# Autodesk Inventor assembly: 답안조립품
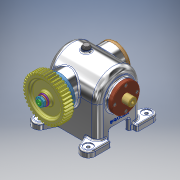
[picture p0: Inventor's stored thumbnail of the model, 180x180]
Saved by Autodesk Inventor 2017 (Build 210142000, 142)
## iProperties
Part Number: 답안조립품
Material: 일반
Document SubType Name: Assembly
Designer: MRC
Author: MRC
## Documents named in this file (17)
- C:\Users\MRC\Downloads\740904V1001\답안조립품.iam
- C:\Users\MRC\Downloads\740904V1001\본체.ipt
- C:\Users\MRC\Downloads\740904V1001\깊은 홈 볼베어링 6203.ipt
- C:\Users\MRC\Downloads\740904V1001\편심축.ipt
- C:\Users\MRC\Downloads\740904V1001\뒷커버.ipt
- C:\Users\MRC\Downloads\740904V1001\앞커버.ipt
- C:\Users\MRC\Downloads\740904V1001\오일실 17 32 8.ipt
- C:\Users\MRC\Downloads\740904V1001\육각 소켓 머리 볼트 M4x10.ipt
- C:\Users\MRC\Downloads\740904V1001\평행키 3x3x14.ipt
- C:\Users\MRC\Downloads\740904V1001\스퍼 기어.ipt
- C:\Users\MRC\Downloads\740904V1001\평와셔 M10.ipt
- C:\Users\MRC\Downloads\740904V1001\스프링와셔 M10.ipt
- C:\Users\MRC\Downloads\740904V1001\육각 너트 M10x1.ipt
- C:\Users\MRC\Downloads\740904V1001\로드.ipt
- C:\Users\MRC\Downloads\740904V1001\부시.ipt
- C:\Users\MRC\Downloads\740904V1001\실링 패드.ipt
- C:\Users\MRC\Downloads\740904V1001\육각 머리 볼트 M6x0.75x12.ipt
